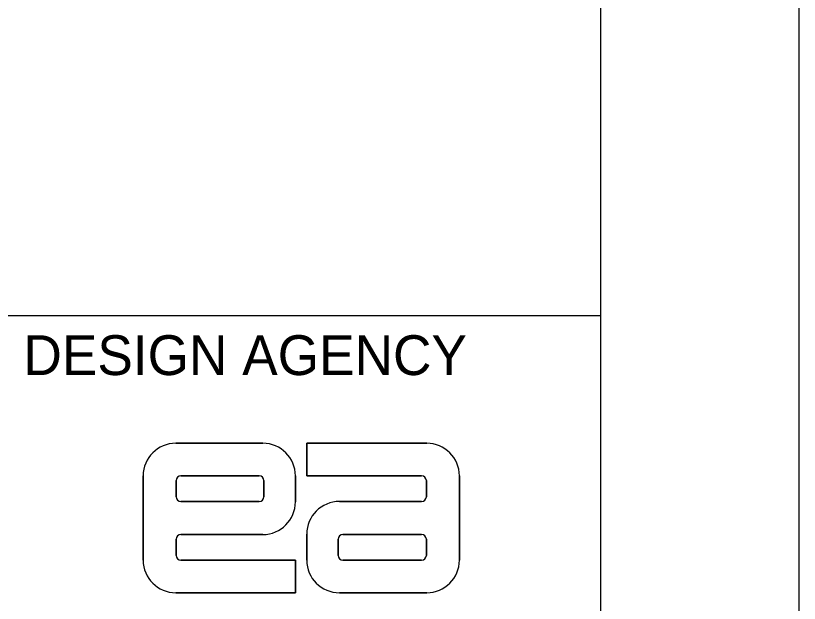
# Model space of a CAD drawing. Extents: x 0 to 34, y 0 to 33.4.
# Drawn here: x 32.03 to 34, y 3.777 to 5.253 of the extents above; entities that cross this region are included whole.
import ezdxf

# ---------------------------------------------------------------- set-up
doc = ezdxf.new("R2010")
doc.units = 0
for name, color, linetype in [('SH_Border', 7, 'Continuous'), ('SH_Cut_Line', 7, 'Continuous'), ('SH_Data', 7, 'Continuous'), ('TX_P_20', 7, 'Continuous')]:
    doc.layers.add(name, color=color, linetype=linetype)

msp = doc.modelspace()

# ---------------------------------------------------------------- linework, layer by layer
at = {"layer": 'SH_Border'}
msp.add_line((32, 4.5), (33.5, 4.5), dxfattribs=at)
msp.add_lwpolyline([(1.5, 21.5), (33.5, 21.5), (33.5, 0.5), (1.5, 0.5)], close=True, dxfattribs=at)
at = {"layer": 'SH_Cut_Line'}
msp.add_lwpolyline([(0, 0), (34, 0), (34, 22), (0, 22)], close=True, dxfattribs=at)
at = {"layer": 'TX_P_20'}
for p, q in [((32.6515, 4.1788), (32.433, 4.1788)), ((32.433, 4.1788), (32.6515, 4.1788)), ((32.762, 4.1788), (33.0635, 4.1788)), ((32.762, 4.0967), (32.762, 4.1788)), ((32.351, 4.0967), (32.351, 3.8852)), ((32.351, 3.8852), (32.351, 4.0967)), ((32.4459, 4.0967), (32.6426, 4.0967)), ((32.6426, 4.0967), (32.4459, 4.0967)), ((32.7336, 4.0315), (32.7336, 4.0967)), ((32.7336, 4.0967), (32.7336, 4.0315)), ((33.0507, 4.0967), (32.762, 4.0967)), ((33.1456, 3.8852), (33.1456, 4.0967)), ((33.1456, 4.0967), (33.1456, 3.8852)), ((32.434, 4.0444), (32.434, 4.0849)), ((32.434, 4.0849), (32.434, 4.0444)), ((32.6545, 4.0849), (32.6545, 4.0444)), ((32.6545, 4.0444), (32.6545, 4.0849)), ((33.0626, 4.0849), (33.0626, 4.0444)), ((33.0626, 4.0444), (33.0626, 4.0849)), ((32.6426, 4.0325), (32.4459, 4.0325)), ((32.4459, 4.0325), (32.6426, 4.0325)), ((33.0507, 4.0325), (32.8441, 4.0325)), ((32.8441, 4.0325), (33.0507, 4.0325)), ((32.4459, 3.9494), (32.6515, 3.9494)), ((32.6515, 3.9494), (32.4459, 3.9494)), ((32.762, 3.9504), (32.762, 3.8852)), ((32.762, 3.8852), (32.762, 3.9504)), ((32.853, 3.9494), (33.0507, 3.9494)), ((33.0507, 3.9494), (32.853, 3.9494)), ((32.434, 3.8971), (32.434, 3.9376)), ((32.434, 3.9376), (32.434, 3.8971)), ((32.8411, 3.8971), (32.8411, 3.9376)), ((32.8411, 3.9376), (32.8411, 3.8971)), ((33.0626, 3.9376), (33.0626, 3.8971)), ((33.0626, 3.8971), (33.0626, 3.9376)), ((32.4459, 3.8852), (32.7336, 3.8852)), ((32.7336, 3.8852), (32.7336, 3.8031)), ((33.0507, 3.8852), (32.853, 3.8852)), ((32.853, 3.8852), (33.0507, 3.8852)), ((32.7336, 3.8031), (32.433, 3.8031)), ((32.8441, 3.8031), (33.0635, 3.8031)), ((33.0635, 3.8031), (32.8441, 3.8031))]:
    msp.add_line(p, q, dxfattribs=at)
for points in [[(33.0635, 4.1788), (32.762, 4.1788), (32.762, 4.0967), (33.0507, 4.0967)], [(32.433, 3.8031), (32.7336, 3.8031), (32.7336, 3.8852), (32.4459, 3.8852)]]:
    msp.add_lwpolyline(points, dxfattribs=at)
for centre, radius, start, end in [((32.433, 4.0967), 0.0821, 90, 180), ((32.433, 4.0967), 0.0821, 90, 180), ((32.6515, 4.0967), 0.0821, 0, 90), ((32.6515, 4.0967), 0.0821, 0, 90), ((33.0635, 4.0967), 0.0821, 0, 90), ((33.0635, 4.0967), 0.0821, 0, 90), ((32.4459, 4.0849), 0.0119, 90, 180), ((32.4459, 4.0849), 0.0119, 90, 180), ((32.6426, 4.0849), 0.0119, 0, 90), ((32.6426, 4.0849), 0.0119, 0, 90), ((33.0507, 4.0849), 0.0119, 0, 90), ((33.0507, 4.0849), 0.0119, 0, 90), ((32.4459, 4.0444), 0.0119, 180, 270), ((32.4459, 4.0444), 0.0119, 180, 270), ((32.6426, 4.0444), 0.0119, 270, 0), ((32.6426, 4.0444), 0.0119, 270, 0), ((33.0507, 4.0444), 0.0119, 270, 0), ((33.0507, 4.0444), 0.0119, 270, 0), ((32.6515, 4.0315), 0.0821, 270, 360), ((32.6515, 4.0315), 0.0821, 270, 360), ((32.8441, 3.9504), 0.0821, 90, 180), ((32.8441, 3.9504), 0.0821, 90, 180), ((32.4459, 3.9376), 0.0119, 90, 180), ((32.4459, 3.9376), 0.0119, 90, 180), ((32.853, 3.9376), 0.0119, 90, 180), ((32.853, 3.9376), 0.0119, 90, 180), ((33.0507, 3.9376), 0.0119, 0, 90), ((33.0507, 3.9376), 0.0119, 0, 90), ((32.433, 3.8852), 0.0821, 180, 270), ((32.433, 3.8852), 0.0821, 180, 270), ((32.4459, 3.8971), 0.0119, 180, 270), ((32.4459, 3.8971), 0.0119, 180, 270), ((32.8441, 3.8852), 0.0821, 180, 270), ((32.8441, 3.8852), 0.0821, 180, 270), ((32.853, 3.8971), 0.0119, 180, 270), ((32.853, 3.8971), 0.0119, 180, 270), ((33.0507, 3.8971), 0.0119, 270, 0), ((33.0507, 3.8971), 0.0119, 270, 0), ((33.0635, 3.8852), 0.0821, 270, 360), ((33.0635, 3.8852), 0.0821, 270, 360)]:
    msp.add_arc(centre, radius, start, end, dxfattribs=at)

# ---------------------------------------------------------------- texts
at = {"layer": 'SH_Data'}
msp.add_text('DESIGN AGENCY', height=0.1, dxfattribs=at).set_placement((32.05, 4.35))

doc.saveas('drawing.dxf')
